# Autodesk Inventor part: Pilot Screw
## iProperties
Shininess: 41.0
Length Units: 11272
Angle Units: 11279
Time Units: 11290
Mass Units: 11286
Length Display Precision: 4
Angle Display Precision: 2
Compacted: True
Company: Autodesk
Manager: Lebovitz
Created: 2000-11
Part Number: Pilot Screw
Document SubType Name: Modeling
Designer: The PD Team
Project: Inventor Samples
Checked By: The PD Team
Density: 0.0
Volumn: 0.0
Area: 0.0
PropertySet Name: Model Information
Control State: 0
Master: False
Checked Out: False
Author: The PD Team
Revision Number: A
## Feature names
1. Revolution1
2. Revolution2
3. Chamfer1
